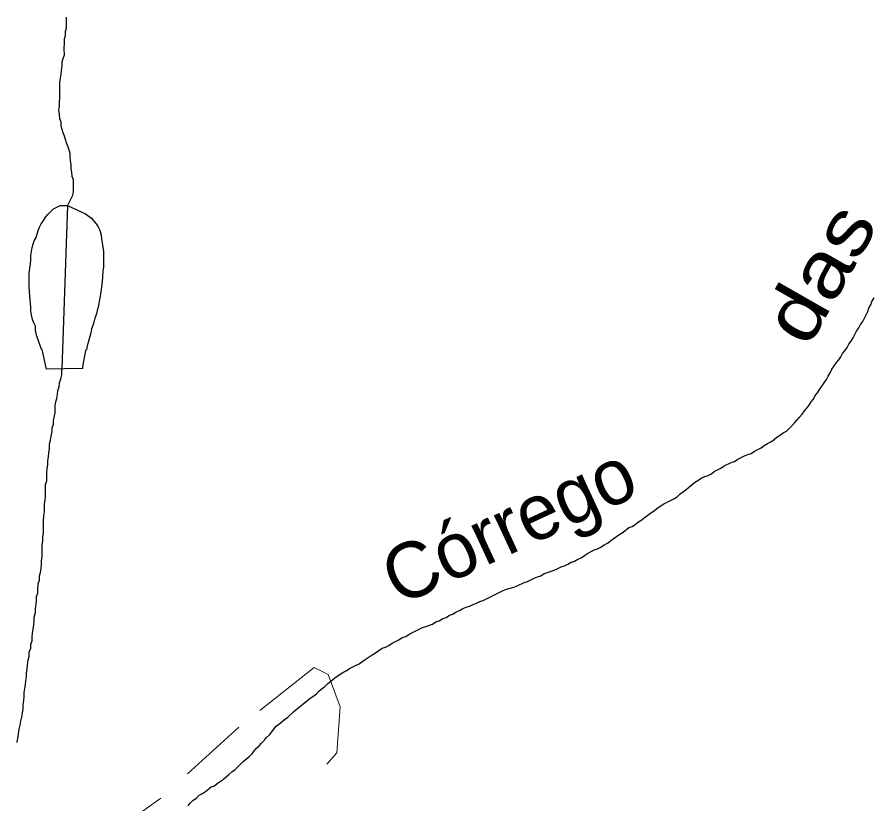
# Model space of a CAD drawing. Extents: x 785.9 to 812.4, y 7674.9 to 7703.1.
# Drawn here: x 795.942 to 797.178, y 7688.275 to 7689.409 of the extents above; entities that cross this region are included whole.
import ezdxf
from ezdxf.enums import TextEntityAlignment as Align

# ---------------------------------------------------------------- set-up
doc = ezdxf.new("R2010")
doc.units = 0
doc.header["$LTSCALE"] = 0.04
doc.linetypes.add('SHORT_DASHED', pattern=[2.7, 1.5, -1.2])
for name, color, linetype, lineweight in [('2', 7, 'Continuous', 25), ('21', 7, 'SHORT_DASHED', 13), ('55', 7, 'Continuous', 25), ('7', 7, 'Continuous', 25)]:
    doc.layers.add(name, color=color, linetype=linetype, lineweight=lineweight)
doc.layers.add('61', color=7, linetype='Continuous')

msp = doc.modelspace()

# ---------------------------------------------------------------- linework, layer by layer
at = {"layer": '2'}
for points in [[(795.9776, 7688.9304), (795.9712, 7688.9474), (795.9696, 7688.9523), (795.9687, 7688.9579), (795.9687, 7688.9636), (795.9663, 7688.9685), (795.9647, 7688.9733), (795.9631, 7688.9798), (795.9623, 7688.9854), (795.9623, 7688.9911), (795.9607, 7689.0073), (795.9598, 7689.0202), (795.9598, 7689.0397), (795.9615, 7689.0534), (795.9623, 7689.0591), (795.9623, 7689.0656), (795.9631, 7689.0712), (795.9639, 7689.0769), (795.9655, 7689.0817), (795.9671, 7689.0866), (795.9696, 7689.0914), (795.9728, 7689.1012), (795.9744, 7689.106), (795.9768, 7689.1109), (795.9801, 7689.1157), (795.9833, 7689.1206), (795.9865, 7689.1246), (795.9946, 7689.1327), (796.0043, 7689.1376), (796.0149, 7689.1376)], [(796.0149, 7689.1376), (796.0408, 7689.1254), (796.0497, 7689.119), (796.0529, 7689.1149), (796.0561, 7689.1109), (796.0594, 7689.1068), (796.0618, 7689.102), (796.0634, 7689.0947), (796.0642, 7689.089), (796.065, 7689.0834), (796.0667, 7689.0712), (796.0667, 7689.0656), (796.0667, 7689.0599), (796.0667, 7689.0542), (796.0667, 7689.0486), (796.0658, 7689.0429), (796.065, 7689.0267), (796.0626, 7689.0097), (796.0618, 7689.0041), (796.0594, 7688.9911), (796.0578, 7688.9863), (796.0561, 7688.9798), (796.0545, 7688.9749), (796.0529, 7688.9693), (796.0513, 7688.9644), (796.0497, 7688.9596), (796.0488, 7688.9539), (796.0448, 7688.9401), (796.0432, 7688.9353), (796.0424, 7688.9296), (796.0411, 7688.9285)], [(796.0411, 7688.9285), (796.0367, 7688.9053), (796.0367, 7688.9053), (796.0364, 7688.9025), (795.9848, 7688.9017), (795.9782, 7688.9297), (795.9776, 7688.9304)]]:
    msp.add_lwpolyline(points, dxfattribs=at)
at = {"layer": '21'}
msp.add_lwpolyline([(796.2564, 7688.1826), (796.4035, 7688.3483), (796.4083, 7688.4146), (796.3908, 7688.4614), (796.3708, 7688.4712), (796.2622, 7688.3854), (796.1497, 7688.283), (796.063, 7688.2216)], dxfattribs=at)
at = {"layer": '55'}
msp.add_line((796.0149, 7689.1376), (796.0069, 7688.902), dxfattribs=at)
at = {"layer": '7'}
for points in [[(796.0132, 7689.409), (796.0132, 7689.3933), (796.0116, 7689.3876), (796.0116, 7689.3819), (796.01, 7689.3771), (796.01, 7689.3714), (796.0099, 7689.3639), (796.01, 7689.3544), (796.0084, 7689.3488), (796.0068, 7689.3439), (796.0068, 7689.3382), (796.006, 7689.3326), (796.0052, 7689.3269), (796.0043, 7689.3212), (796.0035, 7689.3148), (796.0035, 7689.2921), (796.0027, 7689.2864), (796.0027, 7689.2808), (796.0019, 7689.2751), (796.0027, 7689.2695), (796.0035, 7689.263), (796.0052, 7689.2581), (796.0052, 7689.2525), (796.0068, 7689.2476), (796.0084, 7689.2428), (796.01, 7689.2379), (796.0132, 7689.2282), (796.0149, 7689.2233), (796.0181, 7689.2136), (796.0181, 7689.208), (796.0189, 7689.2023), (796.0197, 7689.1966), (796.0197, 7689.191), (796.0205, 7689.1853), (796.0213, 7689.1796), (796.023, 7689.1748), (796.023, 7689.1578), (796.0221, 7689.1521), (796.0149, 7689.1376)], [(797.0999, 7688.8722), (797.1064, 7688.8819), (797.1096, 7688.8867), (797.1121, 7688.8916), (797.1153, 7688.8964), (797.1177, 7688.9013), (797.1242, 7688.911), (797.1274, 7688.9151), (797.1307, 7688.9191), (797.1331, 7688.924), (797.1363, 7688.928), (797.1396, 7688.9329), (797.142, 7688.9377), (797.1452, 7688.9418), (797.1485, 7688.9466), (797.1509, 7688.9515), (797.1533, 7688.9563), (797.1566, 7688.9612), (797.159, 7688.966), (797.1622, 7688.9701), (797.1647, 7688.9749), (797.1671, 7688.9798), (797.1695, 7688.9846), (797.1711, 7688.9895), (797.1736, 7688.9943), (797.1752, 7688.9992), (797.1784, 7689.0041)], [(795.9423, 7688.3633), (795.9424, 7688.3641), (795.9437, 7688.3721), (795.9453, 7688.3826), (795.9469, 7688.3883), (795.9477, 7688.394), (795.9493, 7688.3996), (795.9501, 7688.4053), (795.9509, 7688.4118), (795.9509, 7688.4174), (795.9518, 7688.4239), (795.9526, 7688.4296), (795.9526, 7688.4352), (795.9534, 7688.4409), (795.9542, 7688.4466), (795.955, 7688.4522), (795.9558, 7688.4579), (795.9558, 7688.4636), (795.9566, 7688.4692), (795.9574, 7688.4749), (795.9582, 7688.4822), (795.9598, 7688.487), (795.9598, 7688.4935), (795.9623, 7688.4992), (795.9623, 7688.5048), (795.9639, 7688.5097), (795.9639, 7688.5153), (795.9647, 7688.521), (795.9655, 7688.5267), (795.9663, 7688.5331), (795.9671, 7688.5388), (795.9671, 7688.5445), (795.9687, 7688.5509), (795.9687, 7688.5566), (795.9696, 7688.5623), (795.9704, 7688.5679), (795.9704, 7688.5736), (795.972, 7688.5784), (795.972, 7688.5841), (795.9728, 7688.5922), (795.9744, 7688.5971), (795.9744, 7688.6035), (795.976, 7688.6084), (795.9768, 7688.6141), (795.9776, 7688.6197), (795.9776, 7688.6254), (795.9785, 7688.631), (795.9785, 7688.648), (795.9793, 7688.6537), (795.9793, 7688.6594), (795.9801, 7688.6658), (795.9801, 7688.6828), (795.9809, 7688.6901), (795.9817, 7688.6958), (795.9817, 7688.7071), (795.9825, 7688.7128), (795.9833, 7688.7184), (795.9833, 7688.7354), (795.9849, 7688.7403), (795.9849, 7688.7516), (795.9857, 7688.7581), (795.9865, 7688.7637), (795.9865, 7688.7694), (795.9874, 7688.7751), (795.9882, 7688.7807), (795.989, 7688.7872), (795.989, 7688.7937), (795.9906, 7688.7993), (795.9914, 7688.805), (795.993, 7688.8115), (795.993, 7688.8171), (795.9946, 7688.822), (795.9946, 7688.8277), (795.9972, 7688.8386), (795.9971, 7688.8487), (795.9979, 7688.8544), (795.9995, 7688.8592), (796.0003, 7688.8649), (796.0011, 7688.8706), (796.0027, 7688.8762), (796.0035, 7688.8819), (796.0052, 7688.8875), (796.0068, 7688.8932), (796.0068, 7688.902)], [(796.5707, 7688.5485), (796.5756, 7688.5517), (796.5805, 7688.5534), (796.5853, 7688.5566), (796.5902, 7688.5582), (796.595, 7688.5598), (796.5999, 7688.5623), (796.6047, 7688.5639), (796.6096, 7688.5663), (796.6144, 7688.5679), (796.6436, 7688.5825), (796.6484, 7688.5841), (796.6533, 7688.5857), (796.6589, 7688.5873), (796.6638, 7688.589), (796.6735, 7688.5938), (796.6784, 7688.5954), (796.6881, 7688.6003), (796.6929, 7688.6019), (796.6978, 7688.6035), (796.7026, 7688.6068), (796.7075, 7688.6084), (796.7172, 7688.6116), (796.7221, 7688.6141), (796.7269, 7688.6165), (796.7318, 7688.6181), (796.7366, 7688.6205), (796.7415, 7688.623), (796.7463, 7688.6246), (796.7512, 7688.6278), (796.756, 7688.6294), (796.7609, 7688.6327), (796.7649, 7688.6359), (796.7747, 7688.6408), (796.7795, 7688.6424), (796.7844, 7688.6448), (796.7892, 7688.648), (796.7941, 7688.6505), (796.8022, 7688.6569), (796.807, 7688.6602), (796.8119, 7688.6634), (796.8167, 7688.6666), (796.8248, 7688.6731), (796.8297, 7688.6747), (796.8345, 7688.678), (796.8386, 7688.6812), (796.8434, 7688.6844), (796.8475, 7688.6877), (796.8523, 7688.6909), (796.8564, 7688.6942), (796.8612, 7688.6974), (796.8653, 7688.7006), (796.8701, 7688.7039), (796.875, 7688.7071), (796.8895, 7688.7144), (796.8944, 7688.7176), (796.8985, 7688.7217), (796.9033, 7688.7249), (796.9074, 7688.7281), (796.9114, 7688.7314), (796.9154, 7688.7346), (796.9195, 7688.7379), (796.9243, 7688.7411), (796.9292, 7688.7443), (796.9341, 7688.7468), (796.9389, 7688.7484), (796.9438, 7688.7508), (796.9478, 7688.754), (796.9575, 7688.7589), (796.9624, 7688.7621), (796.9721, 7688.767), (796.9769, 7688.7686), (796.9818, 7688.7718), (796.9866, 7688.7743), (796.9915, 7688.7767), (796.9964, 7688.7783), (797.0012, 7688.7799), (797.0061, 7688.7832), (797.0109, 7688.7856), (797.0158, 7688.788), (797.0198, 7688.7913), (797.0247, 7688.7945), (797.0295, 7688.7969), (797.0344, 7688.8002), (797.0384, 7688.8034), (797.0433, 7688.8066), (797.0473, 7688.8099), (797.0522, 7688.8123), (797.0603, 7688.8204), (797.0643, 7688.8244), (797.0676, 7688.8285), (797.0708, 7688.8325), (797.0748, 7688.8366), (797.0781, 7688.8414), (797.0813, 7688.8455), (797.0846, 7688.8495), (797.0878, 7688.8544), (797.091, 7688.8584), (797.0935, 7688.8633), (797.0967, 7688.8673), (797.0999, 7688.8722)], [(796.1888, 7688.2718), (796.1921, 7688.2758), (796.1961, 7688.2799), (796.201, 7688.2831), (796.205, 7688.2872), (796.2099, 7688.2896), (796.2139, 7688.2928), (796.222, 7688.2993), (796.2269, 7688.3009), (796.2309, 7688.3041), (796.2358, 7688.3074), (796.2398, 7688.3106), (796.2439, 7688.3139), (796.2479, 7688.3171), (796.2519, 7688.3211), (796.2568, 7688.3244), (796.2608, 7688.3284), (796.2689, 7688.3365), (796.273, 7688.3398), (796.277, 7688.343), (796.2811, 7688.347), (796.2843, 7688.3511), (796.2875, 7688.3551), (796.2916, 7688.3584), (796.2948, 7688.3624), (796.2989, 7688.3665), (796.3021, 7688.3705), (796.3062, 7688.3745), (796.3159, 7688.3867), (796.3199, 7688.3899), (796.324, 7688.3932), (796.328, 7688.3964), (796.3329, 7688.3996), (796.341, 7688.4077), (796.345, 7688.411), (796.349, 7688.4142), (796.3571, 7688.4207), (796.3612, 7688.4239), (796.3652, 7688.4271), (796.3701, 7688.4304), (796.3741, 7688.4336), (796.3782, 7688.4377), (796.3822, 7688.4409), (796.3863, 7688.4441), (796.3903, 7688.4482), (796.3944, 7688.4514), (796.3984, 7688.4547), (796.4024, 7688.4579), (796.4122, 7688.4644), (796.417, 7688.4668), (796.4219, 7688.47), (796.4283, 7688.4733), (796.4356, 7688.4765), (796.4397, 7688.4797), (796.4445, 7688.483), (796.4542, 7688.4894), (796.4591, 7688.4927), (796.4639, 7688.4959), (796.4688, 7688.4992), (796.4736, 7688.5008), (796.4785, 7688.5032), (796.4834, 7688.5064), (796.4931, 7688.5113), (796.4979, 7688.5145), (796.5028, 7688.5161), (796.5076, 7688.5194), (796.5125, 7688.5218), (796.5173, 7688.5242), (796.5271, 7688.5291), (796.5319, 7688.5307), (796.5416, 7688.5339), (796.5465, 7688.5372), (796.5513, 7688.5388), (796.5562, 7688.542), (796.561, 7688.5437), (796.5659, 7688.5469), (796.5707, 7688.5485)]]:
    msp.add_lwpolyline(points, dxfattribs=at)

# ---------------------------------------------------------------- texts
at = {"layer": '61', "width": 1.2}
msp.add_text('das', height=0.08, rotation=60.269, dxfattribs=at).set_placement((797.1342, 7689.0204), align=Align.CENTER)
at = {"layer": '61'}
msp.add_text('Córrego', height=0.08, rotation=24.903, dxfattribs=at).set_placement((796.6681, 7688.6407), align=Align.CENTER)

doc.saveas('drawing.dxf')
